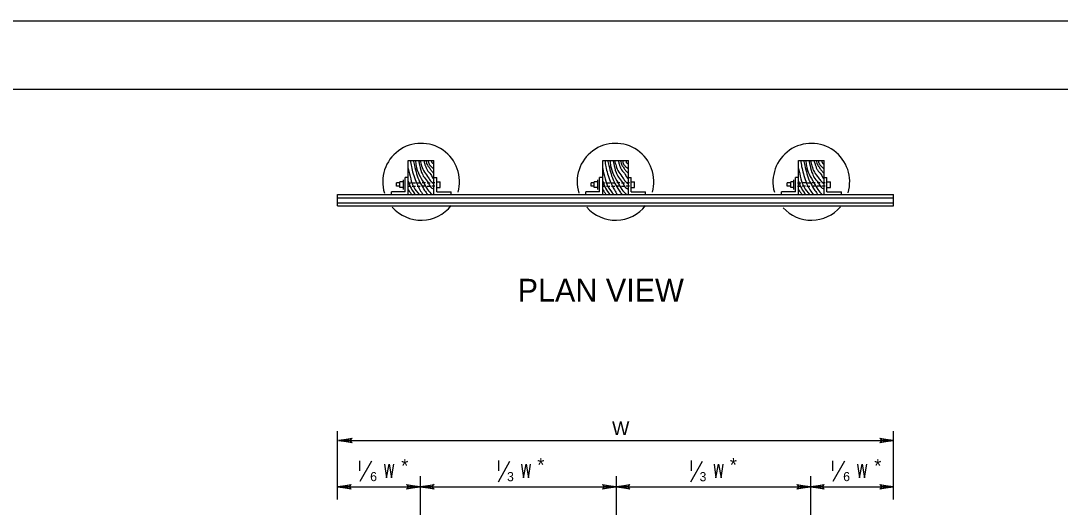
# Model space of a CAD drawing. Extents: x -1958 to 628, y -879 to 309.
# Drawn here: x 130.1 to 357.8, y 203 to 309.4 of the extents above; entities that cross this region are included whole.
import ezdxf

# ---------------------------------------------------------------- set-up
doc = ezdxf.new("R2010")
doc.units = 0
for name, color, linetype in [('1', 7, 'Continuous'), ('2', 7, 'Continuous'), ('3', 7, 'Continuous'), ('PLT-BNDY', 7, 'Continuous')]:
    doc.layers.add(name, color=color, linetype=linetype)

# ---------------------------------------------------------------- blocks, each defined once
blk = doc.blocks.new('RARROW')
at = {"layer": '3'}
blk.add_lwpolyline([(-0.0576, 0.0072), (-0.0555, 0.0031), (0, 0), (-0.0576, 0.0072), (-0.0606, 0.0098), (0, 0), (-0.0555, -0.0027), (-0.0575, -0.0069), (0, 0), (-0.0606, -0.0096), (-0.0575, -0.0069)], dxfattribs=at)

msp = doc.modelspace()

# ---------------------------------------------------------------- linework, layer by layer
at = {"layer": '1'}
msp.add_line((-236.39, 294.44), (549.61, 294.44), dxfattribs=at)
at = {"layer": '2'}
for p, q in [((214.97, 278.88), (220.6, 278.88)), ((257.58, 278.88), (263.2, 278.88)), ((300.5, 278.88), (306.12, 278.88)), ((214.97, 275.13), (214.3, 275.13)), ((220.6, 275.13), (221.2, 275.13)), ((257.58, 275.13), (256.9, 275.13)), ((263.2, 275.13), (263.8, 275.13)), ((300.5, 275.13), (299.82, 275.13)), ((306.12, 275.13), (306.72, 275.13)), ((199.49, 271.38), (321.32, 271.38)), ((214.3, 271.98), (211.3, 271.98)), ((221.2, 271.98), (224.35, 271.98)), ((256.9, 271.98), (253.9, 271.98)), ((263.8, 271.98), (266.95, 271.98)), ((299.82, 271.98), (296.75, 271.98)), ((306.72, 271.98), (309.87, 271.98)), ((199.49, 270.71), (321.32, 270.71)), ((199.49, 269.58), (321.32, 269.58)), ((199.49, 268.91), (321.32, 268.91))]:
    msp.add_line(p, q, dxfattribs=at)
at = {"layer": '3'}
for p, q in [((214.97, 271.38), (214.97, 278.88)), ((220.6, 271.38), (220.6, 278.88)), ((257.58, 271.38), (257.58, 278.88)), ((263.2, 271.38), (263.2, 278.88)), ((300.5, 271.38), (300.5, 278.88)), ((306.12, 271.38), (306.12, 278.88)), ((212.42, 273.26), (212.42, 273.93)), ((213.1, 273.93), (212.42, 273.93)), ((213.1, 272.96), (213.1, 274.16)), ((213.92, 274.16), (213.1, 274.16)), ((213.92, 272.51), (213.92, 274.61)), ((214.3, 271.98), (214.3, 275.13)), ((214.82, 273.93), (215.5, 273.93)), ((215.8, 273.93), (216.55, 273.93)), ((216.92, 273.93), (217.6, 273.93)), ((218.72, 273.93), (218.05, 273.93)), ((219.1, 273.93), (219.77, 273.93)), ((220.82, 273.93), (220.15, 273.93)), ((221.2, 271.98), (221.2, 275.13)), ((221.2, 274.16), (221.95, 274.16)), ((221.95, 272.96), (221.95, 274.16)), ((255.03, 273.26), (255.03, 273.93)), ((255.7, 273.93), (255.03, 273.93)), ((255.7, 272.96), (255.7, 274.16)), ((256.53, 274.16), (255.7, 274.16)), ((256.53, 272.51), (256.53, 274.61)), ((256.9, 271.98), (256.9, 275.13)), ((257.43, 273.93), (258.1, 273.93)), ((258.4, 273.93), (259.15, 273.93)), ((259.53, 273.93), (260.2, 273.93)), ((261.33, 273.93), (260.65, 273.93)), ((261.7, 273.93), (262.38, 273.93)), ((263.43, 273.93), (262.75, 273.93)), ((263.8, 271.98), (263.8, 275.13)), ((263.8, 274.16), (264.55, 274.16)), ((264.55, 272.96), (264.55, 274.16)), ((298.02, 273.26), (298.02, 273.93)), ((298.77, 273.93), (298.02, 273.93)), ((298.77, 272.96), (298.77, 274.16)), ((299.45, 274.16), (298.77, 274.16)), ((299.45, 272.51), (299.45, 274.61)), ((299.82, 271.98), (299.82, 275.13)), ((300.27, 273.93), (301.02, 273.93)), ((302, 273.93), (301.25, 273.93)), ((302.3, 273.93), (302.97, 273.93)), ((304.1, 273.93), (303.42, 273.93)), ((305.22, 273.93), (304.55, 273.93)), ((306.35, 273.93), (305.6, 273.93)), ((306.72, 271.98), (306.72, 275.13)), ((306.72, 274.16), (307.47, 274.16)), ((307.47, 272.96), (307.47, 274.16)), ((199.49, 268.91), (199.49, 271.38)), ((211.3, 271.38), (211.3, 271.98)), ((213.1, 273.26), (212.42, 273.26)), ((213.92, 272.96), (213.1, 272.96)), ((214.82, 273.26), (215.5, 273.26)), ((215.8, 273.26), (216.55, 273.26)), ((216.92, 273.26), (217.6, 273.26)), ((218.72, 273.26), (218.05, 273.26)), ((219.1, 273.26), (219.77, 273.26)), ((220.82, 273.26), (220.15, 273.26)), ((221.2, 272.96), (221.95, 272.96)), ((224.35, 271.38), (224.35, 271.98)), ((253.9, 271.38), (253.9, 271.98)), ((255.7, 273.26), (255.03, 273.26)), ((256.53, 272.96), (255.7, 272.96)), ((257.43, 273.26), (258.1, 273.26)), ((258.4, 273.26), (259.15, 273.26)), ((259.53, 273.26), (260.2, 273.26)), ((261.33, 273.26), (260.65, 273.26)), ((261.7, 273.26), (262.38, 273.26)), ((263.43, 273.26), (262.75, 273.26)), ((263.8, 272.96), (264.55, 272.96)), ((266.95, 271.38), (266.95, 271.98)), ((296.75, 271.38), (296.75, 271.98)), ((298.77, 273.26), (298.02, 273.26)), ((299.45, 272.96), (298.77, 272.96)), ((300.27, 273.26), (301.02, 273.26)), ((302, 273.26), (301.25, 273.26)), ((302.3, 273.26), (302.97, 273.26)), ((304.1, 273.26), (303.42, 273.26)), ((305.22, 273.26), (304.55, 273.26)), ((306.35, 273.26), (305.6, 273.26)), ((306.72, 272.96), (307.47, 272.96)), ((309.87, 271.38), (309.87, 271.98)), ((321.32, 268.91), (321.32, 271.38)), ((199.49, 204.65), (199.49, 219.61)), ((321.32, 204.65), (321.32, 219.61)), ((199.65, 217.56), (321.32, 217.56)), ((217.61, 209.77), (217.61, 193.7)), ((260.53, 209.77), (260.53, 193.7)), ((303.13, 209.77), (303.13, 193.7)), ((199.49, 207.4), (217.61, 207.4)), ((217.61, 207.4), (260.53, 207.4)), ((260.53, 207.4), (303.13, 207.4)), ((303.13, 207.4), (321.32, 207.4))]:
    msp.add_line(p, q, dxfattribs=at)
for points in [[(319.51, 217.8), (319.51, 217.64), (321.32, 217.56), (319.51, 217.8), (319.43, 217.8), (321.32, 217.56), (319.51, 217.48), (319.51, 217.33), (321.32, 217.56), (319.43, 217.33), (319.51, 217.33)], [(204.33, 210.89), (204.33, 213.13)], [(204.45, 208.62), (207, 213.13)], [(209.79, 212.37), (210.21, 209.37), (210.78, 212.37), (211.32, 209.37), (211.8, 212.37)], [(234.71, 208.54), (237.26, 213.05)], [(234.81, 210.92), (234.81, 213.16)], [(239.78, 212.35), (240.2, 209.35), (240.77, 212.35), (241.31, 209.35), (241.78, 212.35)], [(276.9, 208.54), (279.45, 213.05)], [(277, 210.92), (277, 213.16)], [(281.97, 212.35), (282.39, 209.35), (282.96, 212.35), (283.5, 209.35), (283.97, 212.35)], [(307.98, 210.89), (307.98, 213.13)], [(308.1, 208.62), (310.65, 213.13)], [(313.44, 212.37), (313.86, 209.37), (314.43, 212.37), (314.97, 209.37), (315.45, 212.37)]]:
    msp.add_lwpolyline(points, dxfattribs=at)
for centre, start, end in [((217.78, 274.2), 344.085, 197.2873), ((260.38, 274.2), 344.085, 197.2873), ((303.29, 274.2), 343.3743, 195.5154), ((217.78, 274.2), 221.3222, 321.6878), ((260.38, 274.2), 221.3222, 321.6878), ((303.29, 274.2), 222.6593, 319.137)]:
    msp.add_arc(centre, 8.41, start, end, dxfattribs=at)
for points in [[(215.42, 278.88), (215.65, 277.53), (216.02, 275.96), (216.62, 274.31), (217.52, 272.43), (218.2, 271.38)], [(216.02, 278.88), (216.32, 277.76), (217.45, 274.16), (218.27, 272.73), (218.87, 271.83), (219.25, 271.38)], [(216.55, 278.81), (216.7, 277.68), (217.3, 275.88), (218.35, 273.93), (219.17, 272.51), (220.22, 271.38)], [(217.22, 278.88), (217.37, 278.21), (217.9, 276.26), (218.42, 275.21), (219.32, 274.01), (219.85, 273.11), (220.52, 272.58)], [(217.6, 278.81), (217.9, 277.68), (218.5, 276.33), (219.4, 275.06), (219.92, 274.31), (220.52, 273.78)], [(218.42, 278.81), (218.57, 278.06), (218.8, 277.46), (219.1, 276.78), (219.92, 275.81), (220.37, 274.98), (220.52, 274.83)], [(218.87, 278.81), (219.17, 277.83), (219.55, 277.31), (220, 276.63), (220.52, 276.11)], [(219.32, 278.81), (219.55, 278.06), (219.92, 277.61), (220.52, 277.08)], [(220.07, 278.81), (220.15, 278.43), (220.3, 278.28), (220.52, 278.06)], [(258.03, 278.88), (258.25, 277.53), (258.63, 275.96), (259.23, 274.31), (260.13, 272.43), (260.8, 271.38)], [(258.63, 278.88), (258.93, 277.76), (260.05, 274.16), (260.88, 272.73), (261.48, 271.83), (261.85, 271.38)], [(259.15, 278.81), (259.3, 277.68), (259.9, 275.88), (260.95, 273.93), (261.78, 272.51), (262.83, 271.38)], [(259.83, 278.88), (259.98, 278.21), (260.5, 276.26), (261.03, 275.21), (261.93, 274.01), (262.45, 273.11), (263.13, 272.58)], [(260.2, 278.81), (260.5, 277.68), (261.1, 276.33), (262, 275.06), (262.53, 274.31), (263.13, 273.78)], [(261.03, 278.81), (261.18, 278.06), (261.4, 277.46), (261.7, 276.78), (262.53, 275.81), (262.98, 274.98), (263.13, 274.83)], [(261.48, 278.81), (261.78, 277.83), (262.15, 277.31), (262.6, 276.63), (263.13, 276.11)], [(261.93, 278.81), (262.15, 278.06), (262.53, 277.61), (263.13, 277.08)], [(262.68, 278.81), (262.75, 278.43), (262.9, 278.28), (263.13, 278.06)], [(300.95, 278.88), (301.17, 277.53), (301.55, 275.96), (302.07, 274.31), (302.97, 272.43), (303.72, 271.38)], [(301.55, 278.88), (301.85, 277.76), (302.97, 274.16), (303.8, 272.73), (304.4, 271.83), (304.77, 271.38)], [(302.07, 278.81), (302.22, 277.68), (302.82, 275.88), (303.87, 273.93), (304.7, 272.51), (305.67, 271.38)], [(302.75, 278.88), (302.9, 278.21), (303.42, 276.26), (303.87, 275.21), (304.77, 274.01), (305.37, 273.11), (306.05, 272.58)], [(303.12, 278.81), (303.42, 277.68), (303.95, 276.33), (304.85, 275.06), (305.45, 274.31), (306.05, 273.78)], [(303.87, 278.81), (304.1, 278.06), (304.32, 277.46), (304.62, 276.78), (305.45, 275.81), (305.9, 274.98), (306.05, 274.83)], [(304.4, 278.81), (304.7, 277.83), (305.07, 277.31), (305.52, 276.63), (306.05, 276.11)], [(304.77, 278.81), (305.07, 278.06), (305.45, 277.61), (306.05, 277.08)], [(305.6, 278.81), (305.67, 278.43), (305.75, 278.28), (306.05, 278.06)], [(214.97, 277.08), (215.5, 274.83), (216.17, 273.03), (217.37, 271.38)], [(257.58, 277.08), (258.1, 274.83), (258.78, 273.03), (259.98, 271.38)], [(300.5, 277.08), (301.02, 274.83), (301.7, 273.03), (302.9, 271.38)], [(214.97, 274.31), (215.57, 272.81), (216.55, 271.38)], [(257.58, 274.31), (258.18, 272.81), (259.15, 271.38)], [(300.5, 274.31), (301.1, 272.81), (302.07, 271.38)], [(214.97, 272.51), (215.42, 271.83), (215.8, 271.31)], [(257.58, 272.51), (258.03, 271.83), (258.4, 271.31)], [(300.5, 272.51), (300.95, 271.83), (301.32, 271.31)]]:
    msp.add_spline(points, degree=3, dxfattribs=at)
at = {"layer": 'PLT-BNDY'}
msp.add_lwpolyline([(-276.39, 309.44), (564.61, 309.44), (564.61, -284.56), (-276.39, -284.56)], close=True, dxfattribs=at)

# ---------------------------------------------------------------- block references
at = {"layer": '2', "xscale": 49.50530586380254, "yscale": 51.54709073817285, "rotation": 180}
for p in [(199.65, 217.56), (199.49, 207.4), (217.61, 207.4), (260.52, 207.4), (303.13, 207.4)]:
    msp.add_blockref('RARROW', p, dxfattribs=at)
at = {"layer": '2', "xscale": 49.50530586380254, "yscale": 51.54709073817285}
for p in [(321.32, 217.56), (217.61, 207.4), (260.52, 207.4), (303.13, 207.4), (321.32, 207.4)]:
    msp.add_blockref('RARROW', p, dxfattribs=at)

# ---------------------------------------------------------------- texts
at = {"layer": '2'}
for p in [(213.42, 210.53), (243.24, 210.73), (285.43, 210.73), (317.07, 210.53)]:
    msp.add_text('*', height=3, dxfattribs=at).set_placement(p)
at = {"layer": '3'}
for s, height, p in [('PLAN VIEW', 5, (238.94, 247.95)), ('W', 3, (259.63, 218.74)), ('6', 2, (206.62, 208.66)), ('3', 2, (236.61, 208.64)), ('3', 2, (278.8, 208.64)), ('6', 2, (310.27, 208.66))]:
    msp.add_text(s, height=height, dxfattribs=at).set_placement(p)

doc.saveas('drawing.dxf')
